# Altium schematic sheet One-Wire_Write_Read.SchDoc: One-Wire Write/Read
size A4; DocumentNumber: 9; SheetNumber: 9; SheetTotal: 12
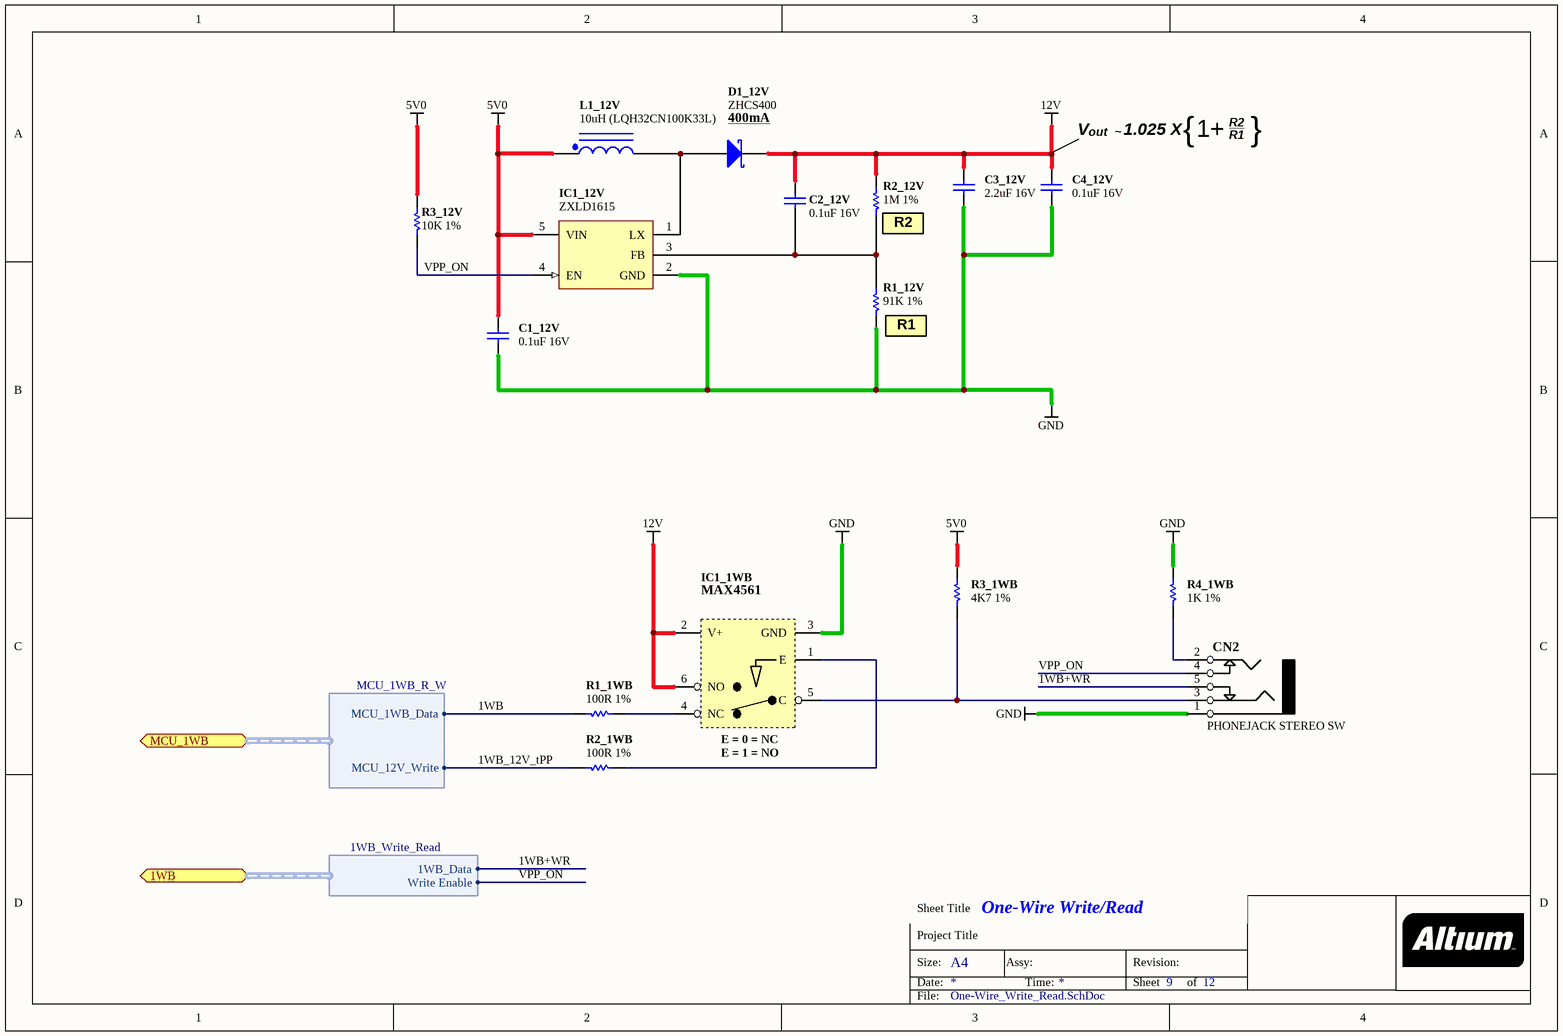
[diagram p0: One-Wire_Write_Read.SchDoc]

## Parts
C1_12V  0.1uF 16V  [CAPC1005-STAR]
C2_12V  0.1uF 16V  [CAPC1005-STAR]
C3_12V  2.2uF 16V  [CAPC2012-STAR]
C4_12V  0.1uF 16V  [CAPC1005-STAR]
CN2  PHONEJACK STEREO SW  [STX-2550-5N-TR]
D1_12V  ZHCS400  [SOD323]
IC1_1WB  MAX4561  [SOT23-6]
IC1_12V  ZXLD1615  [SOT-23-5]
L1_12V  10uH (LQH32CN100K33L)  [3261]
R1_1WB  100R 1%  [RESC1005-STAR]
R1_12V  91K 1%  [RESC1005-STAR]
R2_1WB  100R 1%  [RESC1005-STAR]
R2_12V  1M 1%  [RESC1005-STAR]
R3_1WB  4K7 1%  [RESC1005-STAR]
R3_12V  10K 1%  [RESC1005-STAR]
R4_1WB  1K 1%  [RESC1005-STAR]

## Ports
1WB (harness 1WB_Write_Read), MCU_1WB (harness MCU_1WB_R_W)

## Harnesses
1WB_Write_Read: 1WB_Data, Write Enable
MCU_1WB_R_W: MCU_1WB_Data, MCU_12V_Write

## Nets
5V0: C1_12V.2 IC1_12V.5(VIN) L1_12V.1 R3_1WB.2 R3_12V.1
12V: C2_12V.2 C3_12V.2 C4_12V.2 D1_12V.2(K) IC1_1WB.2(V+) IC1_1WB.6(NO) R2_12V.2
GND: C1_12V.1 C3_12V.1 C4_12V.1 CN2.1 IC1_1WB.3(GND) IC1_12V.2(GND) R1_12V.1 R4_1WB.2
1WB: R1_1WB.1 ; port MCU_1WB.MCU_1WB_Data
1WB+WR: CN2.5 ; port 1WB.1WB_Data
1WB_12V_tPP: R2_1WB.1 ; port MCU_1WB.MCU_12V_Write
VPP_ON: CN2.4 IC1_12V.4(EN) R3_12V.2 ; port 1WB.Write Enable
NetC2_12V_1: C2_12V.1 IC1_12V.3(FB) R1_12V.2 R2_12V.1
NetCN2_2: CN2.2 R4_1WB.1
NetCN2_3: CN2.3 IC1_1WB.5(C) R3_1WB.1
NetD1_12V_1: D1_12V.1(A) IC1_12V.1(LX) L1_12V.2
NetIC1_1WB_1: IC1_1WB.1(E) R2_1WB.2
NetIC1_1WB_4: IC1_1WB.4(NC) R1_1WB.2

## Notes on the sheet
- (near D1_12V) 400mA
- (near C4_12V) V
- out  ~
- 1.025 X
- {
- 1+
- R2
- R1
- }
- (near R2_12V) R2
- (near R1_12V) R1
- (near IC1_1WB) E = 0 = NC
- (near IC1_1WB) E = 1 = NO

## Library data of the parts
C1_12V C2_12V C4_12V = D-101-0080: Capacitor, Ceramic, 0.1uF 10% 16V 0402 (1005) X7R; Polarity: Non-Polarized
C3_12V = D-101-0000: Capacitor, Ceramic, 2.2uF 10% 16V 0805 (2012) X5R; Polarity: Non-Polarized
CN2 = D-300-0059: Connector type: Header; Max Current: mA
D1_12V = D-151-0004: Schottky Diode, 400mA; Rated Voltage: mV
IC1_1WB = D-200-0003: ¡À15kV ESD-Protected, Low-Voltage,  SPDT, CMOS Analog Switches; Supply Voltage: mV
IC1_12V = D-204-0017: ADJUSTABLE DC-DC BOOST CONVERTER WITH INTERNAL SWITCH IN  TSOT23-5; Max Input Voltage: 5.5 V; Max Output Current: 250 mA; Max Output Voltage: 28 V; Min Input Voltage: mV
L1_12V = D-102-0011: Inductor, 10uH, 450mA, 0.3R, 1210 (3225) LQH32CN100K33L
R1_1WB R2_1WB = D-100-0131: Resistor, 100R 1% 0402 (1005); Power Rating: 63 mW
R1_12V = D-100-0073: Resistor, 91K 1% 0402; Power Rating: mW; Resistance: mR; Tolerance: %
R2_12V = D-100-0075: Resistor, 1M 1% 0402; Power Rating: mW; Resistance: mR; Tolerance: %
R3_1WB = D-100-0088: Resistor, 4K7 1% 0402 (1005); Power Rating: 63 mW; Resistance: 4.7 K
R3_12V = D-100-0130: Resistor, 10K 1% 0402 (1005); Power Rating: 63 mW
R4_1WB = D-100-0121: Resistor, 1K 1% 0402 (1005); Power Rating: 63 mW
